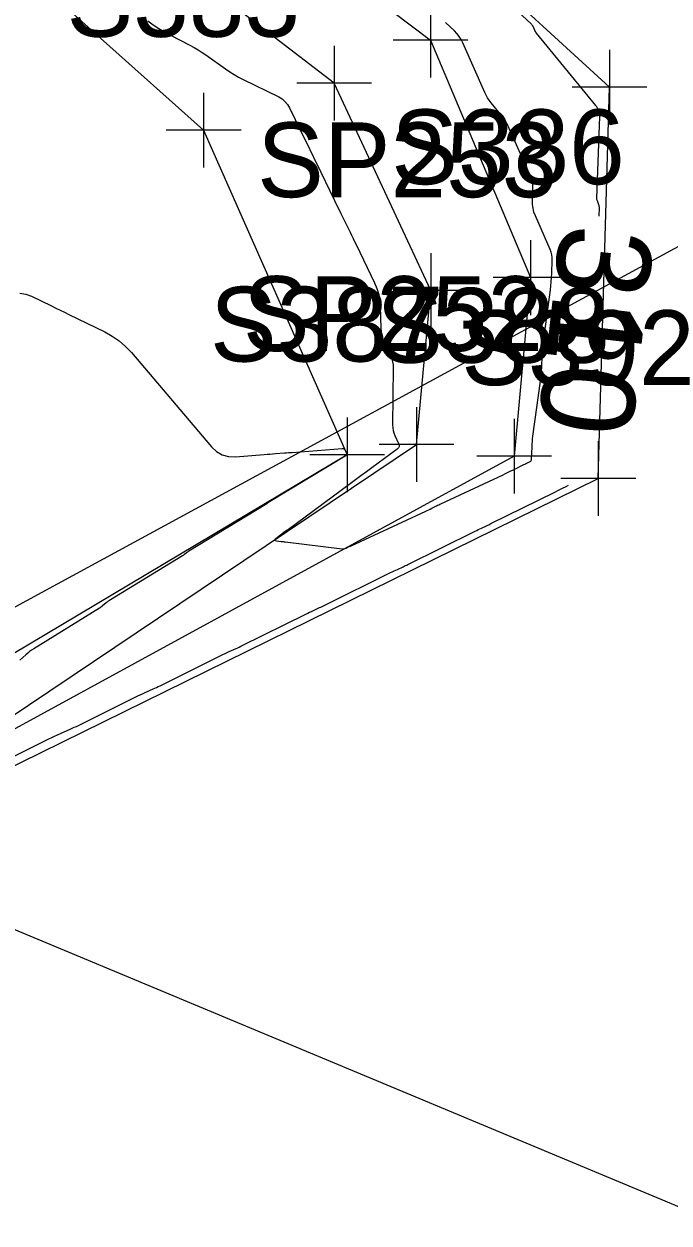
# Model space of a CAD drawing. Extents: x 816928 to 825690, y 436959 to 448212.
# Drawn here: x 818949.5 to 818984, y 445002.2 to 445066.4 of the extents above; entities that cross this region are included whole.
import ezdxf

# ---------------------------------------------------------------- set-up
doc = ezdxf.new("R2010")
doc.units = 0
for name, color, linetype in [('SURVEY - CENTERLINE - Preliminary', 7, 'Continuous'), ('SURVEY - CONTOURS - Index with Text', 7, 'Continuous'), ('SURVEY - CONTOURS - Intermediate with optional Text', 7, 'Continuous'), ('SURVEY - DRAINAGE - Area Shapes', 7, 'Continuous'), ('SURVEY - DTM - Breaklines', 7, 'Continuous'), ('SURVEY - DTM - Breaklines - Points - Locators', 7, 'Continuous'), ('SURVEY - DTM - Breaklines - Points - Numbers', 7, 'Continuous'), ('SURVEY - NON-TRANSPORTATION - Features', 7, 'Continuous'), ('SURVEY - PROPERTY - Parcels', 7, 'Continuous'), ('SURVEY - PROPERTY - ROW Lines', 7, 'Continuous'), ('SURVEY - VEGETATION - Features with Text', 7, 'Continuous')]:
    doc.layers.add(name, color=color, linetype=linetype)

msp = doc.modelspace()

# ---------------------------------------------------------------- linework, layer by layer
at = {"layer": 'SURVEY - CENTERLINE - Preliminary'}
msp.add_arc((819561.099, 444735.998), 738, 144.598464, 158.728454, dxfattribs=at)
msp.add_arc((819561.099, 444735.998), 738, 144.598464, 158.728454, dxfattribs=at)
at = {"layer": 'SURVEY - CONTOURS - Index with Text'}
for points in [[(818980.267, 445056.086), (818980.283, 445056.555), (818980.282, 445056.607), (818980.276, 445056.657), (818980.263, 445056.706), (818980.245, 445056.754), (818980.177, 445056.908), (818980.165, 445056.942), (818980.156, 445056.976), (818980.152, 445057.011), (818980.151, 445057.047), (818980.315, 445061.429), (818980.314, 445061.492), (818980.306, 445061.554), (818980.29, 445061.614), (818980.268, 445061.673), (818980.183, 445061.862), (818980.163, 445061.902), (818980.141, 445061.941), (818980.117, 445061.977), (818980.09, 445062.013), (818976.923, 445065.888), (818976.89, 445065.931), (818976.86, 445065.977), (818976.833, 445066.024), (818976.81, 445066.073), (818976.738, 445066.236), (818976.721, 445066.269), (818976.701, 445066.301), (818976.677, 445066.331), (818976.651, 445066.358), (818973.37, 445069.441)], [(818949.273, 445051.971), (818949.589, 445051.922), (818949.902, 445051.805), (818950.976, 445051.283), (818951.206, 445051.171), (818951.436, 445051.059), (818951.666, 445050.947), (818951.896, 445050.835), (818953.826, 445049.896), (818954.225, 445049.676), (818954.595, 445049.419), (818954.936, 445049.124), (818955.248, 445048.793), (818959.526, 445043.753), (818959.798, 445043.494), (818960.104, 445043.318), (818960.445, 445043.225), (818960.82, 445043.214), (818962.353, 445043.333), (818962.502, 445043.345), (818962.651, 445043.357), (818962.801, 445043.368), (818962.95, 445043.38), (818963.438, 445043.418), (818963.543, 445043.426), (818963.647, 445043.434), (818963.752, 445043.442), (818963.856, 445043.45), (818966.516, 445043.657), (818966.57, 445043.655), (818966.616, 445043.638), (818966.653, 445043.606), (818966.682, 445043.56), (818966.797, 445043.315), (818966.797, 445043.314), (818966.797, 445043.313), (818966.797, 445043.312), (818966.796, 445043.311), (818966.793, 445043.309), (818966.792, 445043.308), (818966.792, 445043.308), (818966.791, 445043.307), (818966.79, 445043.307), (818966.783, 445043.302), (818966.781, 445043.3), (818966.78, 445043.299), (818966.778, 445043.298), (818966.776, 445043.297), (818962.545, 445040.741), (818962.53, 445040.732), (818962.514, 445040.722), (818962.5, 445040.711), (818962.485, 445040.7), (818962.437, 445040.664), (818962.427, 445040.657), (818962.417, 445040.649), (818962.406, 445040.642), (818962.395, 445040.635), (818958.319, 445038.161), (818958.284, 445038.139), (818958.25, 445038.116), (818958.217, 445038.092), (818958.185, 445038.068), (818958.08, 445037.985), (818958.058, 445037.967), (818958.035, 445037.951), (818958.011, 445037.935), (818957.987, 445037.919), (818954.132, 445035.563), (818954.069, 445035.522), (818954.007, 445035.48), (818953.947, 445035.435), (818953.889, 445035.388), (818953.702, 445035.231), (818953.661, 445035.198), (818953.619, 445035.167), (818953.576, 445035.137), (818953.532, 445035.108), (818950.019, 445032.938), (818949.908, 445032.866), (818949.801, 445032.79), (818949.697, 445032.708), (818949.598, 445032.621), (818949.278, 445032.33)], [(818948.107, 445026.768), (818950.825, 445028.115), (818950.98, 445028.191), (818951.136, 445028.265), (818951.294, 445028.338), (818951.452, 445028.408), (818951.97, 445028.634), (818952.08, 445028.683), (818952.19, 445028.734), (818952.3, 445028.785), (818952.409, 445028.838), (818955.452, 445030.346), (818955.582, 445030.41), (818955.713, 445030.472), (818955.844, 445030.533), (818955.976, 445030.593), (818956.408, 445030.787), (818956.501, 445030.829), (818956.593, 445030.871), (818956.684, 445030.915), (818956.776, 445030.96), (818960.03, 445032.571), (818960.143, 445032.626), (818960.257, 445032.681), (818960.371, 445032.734), (818960.485, 445032.787), (818960.86, 445032.958), (818960.94, 445032.994), (818961.019, 445033.032), (818961.099, 445033.07), (818961.178, 445033.109), (818964.581, 445034.793), (818964.682, 445034.842), (818964.783, 445034.891), (818964.884, 445034.939), (818964.986, 445034.986), (818965.318, 445035.139), (818965.39, 445035.172), (818965.46, 445035.206), (818965.531, 445035.24), (818965.602, 445035.275), (818969.115, 445037.013), (818969.206, 445037.057), (818969.298, 445037.102), (818969.389, 445037.145), (818969.481, 445037.188), (818969.783, 445037.328), (818969.847, 445037.358), (818969.911, 445037.389), (818969.975, 445037.42), (818970.039, 445037.451), (818973.637, 445039.231), (818973.721, 445039.272), (818973.805, 445039.313), (818973.889, 445039.353), (818973.974, 445039.393), (818974.25, 445039.522), (818974.31, 445039.55), (818974.369, 445039.578), (818974.427, 445039.607), (818974.486, 445039.636), (818977.899, 445041.323), (818978.103, 445041.424), (818978.307, 445041.525), (818978.512, 445041.626), (818978.633, 445041.686)]]:
    msp.add_lwpolyline(points, dxfattribs=at)
at = {"layer": 'SURVEY - CONTOURS - Intermediate with optional Text'}
msp.add_lwpolyline([(818956.119, 445066.537), (818956.412, 445066.331), (818956.713, 445066.137), (818957.021, 445065.954), (818957.336, 445065.782), (818958.376, 445065.241), (818958.597, 445065.121), (818958.813, 445064.994), (818959.025, 445064.859), (818959.232, 445064.718), (818960.281, 445063.973), (818960.508, 445063.818), (818960.742, 445063.672), (818960.98, 445063.536), (818961.225, 445063.409), (818963.13, 445062.469), (818963.31, 445062.362), (818963.464, 445062.231), (818963.594, 445062.075), (818963.699, 445061.895), (818964.003, 445061.266), (818964.068, 445061.131), (818964.133, 445060.997), (818964.199, 445060.862), (818964.265, 445060.728), (818964.734, 445059.779), (818964.834, 445059.575), (818964.934, 445059.372), (818965.033, 445059.168), (818965.132, 445058.963), (818966.115, 445056.925), (818966.228, 445056.691), (818966.342, 445056.458), (818966.456, 445056.225), (818966.571, 445055.992), (818966.946, 445055.231), (818967.026, 445055.068), (818967.106, 445054.904), (818967.186, 445054.741), (818967.265, 445054.577), (818968.253, 445052.528), (818968.382, 445052.219), (818968.477, 445051.903), (818968.536, 445051.577), (818968.561, 445051.244), (818968.584, 445050.123), (818968.601, 445049.898), (818968.641, 445049.678), (818968.705, 445049.464), (818968.793, 445049.256), (818969.117, 445048.586), (818969.178, 445048.44), (818969.22, 445048.29), (818969.245, 445048.137), (818969.253, 445047.979), (818969.22, 445044.91), (818969.227, 445044.766), (818969.249, 445044.626), (818969.287, 445044.49), (818969.34, 445044.357), (818969.541, 445043.928), (818969.568, 445043.84), (818969.565, 445043.76), (818969.53, 445043.687), (818969.464, 445043.623), (818968.106, 445042.62), (818967.816, 445042.405), (818967.525, 445042.191), (818967.234, 445041.976), (818966.943, 445041.761), (818963.644, 445039.324), (818963.628, 445039.312), (818963.612, 445039.301), (818963.595, 445039.29), (818963.579, 445039.28), (818963.523, 445039.246), (818963.511, 445039.239), (818963.5, 445039.231), (818963.488, 445039.223), (818963.477, 445039.215), (818962.972, 445038.83), (818962.927, 445038.787), (818962.917, 445038.753), (818962.943, 445038.73), (818963.003, 445038.715), (818963.26, 445038.684), (818963.315, 445038.678), (818963.37, 445038.671), (818963.425, 445038.665), (818963.48, 445038.658), (818966.53, 445038.291), (818966.582, 445038.289), (818966.632, 445038.293), (818966.682, 445038.304), (818966.73, 445038.323), (818966.94, 445038.42), (818966.947, 445038.423), (818966.953, 445038.426), (818966.959, 445038.429), (818966.966, 445038.432), (818966.987, 445038.442), (818966.991, 445038.445), (818966.996, 445038.447), (818967.001, 445038.449), (818967.005, 445038.451), (818970.991, 445040.303), (818971.072, 445040.341), (818971.152, 445040.379), (818971.233, 445040.418), (818971.313, 445040.458), (818971.575, 445040.587), (818971.631, 445040.615), (818971.688, 445040.642), (818971.744, 445040.669), (818971.801, 445040.696), (818975.131, 445042.254), (818975.271, 445042.32), (818975.41, 445042.386), (818975.55, 445042.454), (818975.689, 445042.522), (818976.24, 445042.795), (818976.288, 445042.819), (818976.336, 445042.842), (818976.384, 445042.866), (818976.432, 445042.89), (818976.589, 445042.967), (818976.618, 445042.987), (818976.64, 445043.011), (818976.653, 445043.041), (818976.659, 445043.076), (818976.683, 445043.748), (818976.69, 445043.891), (818976.701, 445044.035), (818976.715, 445044.178), (818976.733, 445044.321), (818977.138, 445047.262), (818977.161, 445047.447), (818977.179, 445047.633), (818977.193, 445047.819), (818977.202, 445048.005), (818977.224, 445048.614), (818977.23, 445048.745), (818977.239, 445048.875), (818977.252, 445049.005), (818977.267, 445049.134), (818977.667, 445052.152), (818977.693, 445052.367), (818977.713, 445052.584), (818977.729, 445052.801), (818977.739, 445053.018), (818977.764, 445053.728), (818977.761, 445053.879), (818977.741, 445054.026), (818977.705, 445054.17), (818977.652, 445054.311), (818976.861, 445056.11), (818976.787, 445056.308), (818976.736, 445056.51), (818976.709, 445056.717), (818976.705, 445056.929), (818976.731, 445057.626), (818976.728, 445057.774), (818976.709, 445057.919), (818976.673, 445058.06), (818976.62, 445058.199), (818975.463, 445060.784), (818975.361, 445060.993), (818975.246, 445061.194), (818975.118, 445061.387), (818974.977, 445061.572), (818974.494, 445062.163), (818974.395, 445062.292), (818974.306, 445062.427), (818974.226, 445062.568), (818974.155, 445062.715), (818972.981, 445065.369), (818972.892, 445065.547), (818972.787, 445065.713), (818972.665, 445065.867), (818972.528, 445066.01), (818972.051, 445066.458)], dxfattribs=at)
at = {"layer": 'SURVEY - DRAINAGE - Area Shapes'}
msp.add_arc((819561.099, 444735.998), 738, 144.598464, 158.728454, dxfattribs=at)
at = {"layer": 'SURVEY - DTM - Breaklines'}
for points in [[(818948.142, 445082.95), (818971.253, 445065.506), (818976.595, 445052.8), (818975.731, 445043.247), (818942.824, 445025.275), (818970.496, 445043.876), (818971.261, 445052.107), (818966.093, 445063.21), (818943.888, 445080.247)], [(818914.334, 445030.823), (818915.452, 445029.695), (818923.321, 445029.178), (818930.281, 445034.637), (818931.017, 445049.778), (818943.086, 445046.701), (818934.118, 445057.221), (818940.718, 445077.122), (818959.11, 445060.691), (818966.789, 445043.311), (818943.454, 445029.425), (818938.29, 445021.421), (818980.228, 445042.05), (818980.825, 445062.99), (818966.168, 445076.431)]]:
    msp.add_lwpolyline(points, dxfattribs=at)
at = {"layer": 'SURVEY - DTM - Breaklines - Points - Locators'}
for p, q in [((818971.253, 445067.506), (818971.253, 445063.506)), ((818966.093, 445065.21), (818966.093, 445061.21)), ((818973.253, 445065.506), (818969.253, 445065.506)), ((818980.825, 445064.99), (818980.825, 445060.99)), ((818968.093, 445063.21), (818964.093, 445063.21)), ((818959.11, 445062.691), (818959.11, 445058.691)), ((818982.825, 445062.99), (818978.825, 445062.99)), ((818961.11, 445060.691), (818957.11, 445060.691)), ((818976.595, 445054.8), (818976.595, 445050.8)), ((818971.261, 445054.107), (818971.261, 445050.107)), ((818978.595, 445052.8), (818974.595, 445052.8)), ((818973.261, 445052.107), (818969.261, 445052.107)), ((818970.496, 445045.876), (818970.496, 445041.876)), ((818966.789, 445045.311), (818966.789, 445041.311)), ((818975.731, 445045.247), (818975.731, 445041.247)), ((818980.228, 445044.05), (818980.228, 445040.05)), ((818968.789, 445043.311), (818964.789, 445043.311)), ((818972.496, 445043.876), (818968.496, 445043.876)), ((818977.731, 445043.247), (818973.731, 445043.247)), ((818982.228, 445042.05), (818978.228, 445042.05))]:
    msp.add_line(p, q, dxfattribs=at)
at = {"layer": 'SURVEY - NON-TRANSPORTATION - Features'}
msp.add_lwpolyline([(819140.689, 445080.529), (819097.737, 445097.538), (819000.89, 445063.371), (818928.914, 445024.247)], dxfattribs=at)
at = {"layer": 'SURVEY - PROPERTY - Parcels'}
msp.add_arc((819561.099, 444735.998), 713, 144.598464, 158.728454, dxfattribs=at)
at = {"layer": 'SURVEY - PROPERTY - ROW Lines'}
msp.add_arc((819561.099, 444735.998), 713, 144.598464, 158.728454, dxfattribs=at)
msp.add_arc((819561.099, 444735.998), 713, 144.598464, 158.728454, dxfattribs=at)
at = {"layer": 'SURVEY - VEGETATION - Features with Text'}
msp.add_lwpolyline([(819138.426, 445046.447), (819032.912, 444982.873), (818910.972, 445033.765), (818932.797, 445097.219)], dxfattribs=at)

# ---------------------------------------------------------------- texts
at = {"layer": 'SURVEY - CONTOURS - Index with Text'}
msp.add_text('310', height=5, rotation=263.5253, dxfattribs=at).set_placement((818978.254, 445055.779))
at = {"layer": 'SURVEY - DTM - Breaklines - Points - Numbers'}
for s, p in [('S383', (818951.774, 445065.691)), ('S386', (818969.149, 445057.8)), ('SP253', (818961.973, 445057.107)), ('SP252', (818961.208, 445048.876)), ('S387', (818959.453, 445048.311)), ('S388', (818968.348, 445048.247)), ('S392', (818972.892, 445047.05))]:
    msp.add_text(s, height=4, dxfattribs=at).set_placement(p)

doc.saveas('drawing.dxf')
